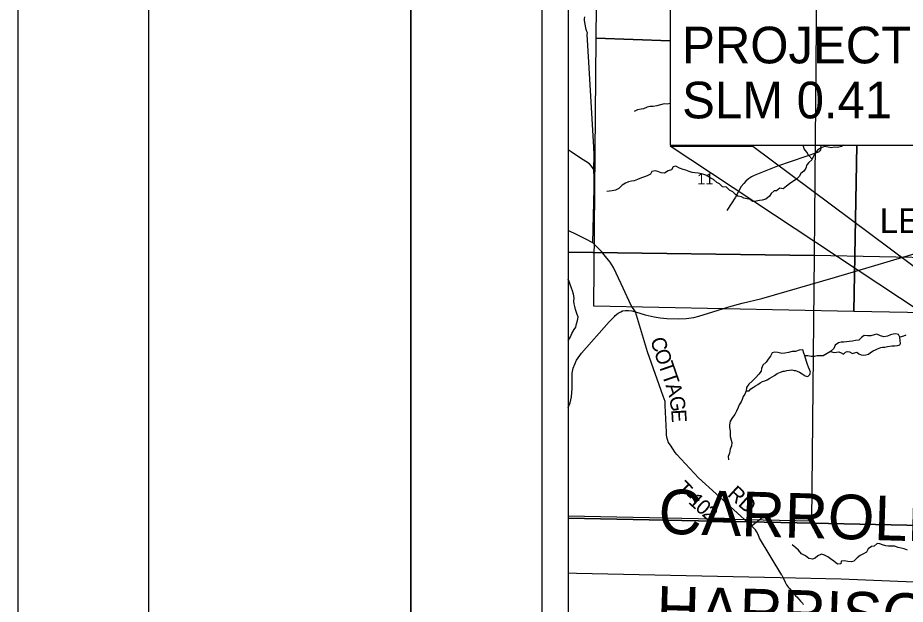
# Model space of a CAD drawing. Extents: x -19.9 to 41.9, y 0 to 32.3.
# Drawn here: x 0 to 3.386, y 17.59 to 19.829 of the extents above; entities that cross this region are included whole.
import ezdxf

# ---------------------------------------------------------------- set-up
doc = ezdxf.new("R2010")
doc.units = 0
for name, color, linetype in [('GM_X_Corporation', 7, 'Continuous'), ('GM_X_Corporation_Text', 7, 'Continuous'), ('GM_X_County', 7, 'Continuous'), ('GM_X_County_Road', 7, 'Continuous'), ('GM_X_County_Text', 7, 'Continuous'), ('GM_X_Minor_Lake', 7, 'Continuous'), ('GM_X_Minor_River', 7, 'Continuous'), ('GM_X_Section', 7, 'Continuous'), ('GM_X_Section_Text', 7, 'Continuous'), ('GM_X_Township_Road', 7, 'Continuous'), ('GM_X_Township_Road_Text', 7, 'Continuous'), ('SH_Border', 7, 'Continuous'), ('SH_Cut_Line', 7, 'Continuous'), ('SH_Data', 7, 'Continuous'), ('SH_Text', 7, 'Continuous')]:
    doc.layers.add(name, color=color, linetype=linetype)

msp = doc.modelspace()

# ---------------------------------------------------------------- linework, layer by layer
at = {"layer": 'GM_X_Corporation'}
for points in [[(8.9, 17.8974), (8.9, 20.9), (2.1, 20.9), (2.1, 17.918), (2.4715, 17.9106), (2.973, 17.9007), (3.7505, 17.884), (3.984, 17.879), (4.2613, 17.8672), (4.9169, 17.8392), (5.0192, 17.8403), (5.0257, 17.9637), (5.4954, 17.9559), (5.761, 17.9543), (5.9048, 17.9534), (6.2397, 17.9517), (6.2497, 17.9517), (6.3069, 17.9505), (6.7, 17.9422), (6.9468, 17.937), (7.3858, 17.9277), (7.5529, 17.9242), (7.9072, 17.9171)], [(2.1, 19.9743), (2.1, 18.9334), (3.0393, 18.921), (3.0491, 19.9448)], [(3.0491, 19.9448), (4.0503, 19.9079), (4.0319, 18.9009), (3.0393, 18.921)], [(2.1, 18.9334), (2.1, 17.9274), (3.0296, 17.9081), (3.0393, 18.921)], [(2.1, 17.918), (2.1, 14.1), (8.9, 14.1), (8.9, 17.8974), (7.9072, 17.9171), (7.5529, 17.9242), (7.3858, 17.9277), (6.9468, 17.937), (6.7, 17.9422), (6.3069, 17.9505), (6.2497, 17.9517), (6.2397, 17.9517), (5.9048, 17.9534), (5.761, 17.9543), (5.4954, 17.9559), (5.0257, 17.9637), (5.0192, 17.8403), (4.9169, 17.8392), (4.2613, 17.8672), (3.984, 17.879), (3.7505, 17.884), (2.973, 17.9007), (2.4715, 17.9106)]]:
    msp.add_lwpolyline(points, close=True, dxfattribs=at)
for points in [[(7.9833, 20.9), (2.1, 20.9), (2.1, 17.918), (2.4715, 17.9106), (2.973, 17.9007), (3.7505, 17.884)], [(7.9012, 17.4524), (7.9072, 17.9171), (7.5529, 17.9242), (7.3858, 17.9277), (6.9468, 17.937), (6.7, 17.9422), (6.3069, 17.9505), (6.2497, 17.9517), (6.2397, 17.9517), (5.9048, 17.9534), (5.761, 17.9543), (5.4954, 17.9559), (5.0257, 17.9637), (5.0192, 17.8403), (4.9169, 17.8392), (4.2613, 17.8672), (3.984, 17.879), (3.7505, 17.884), (2.973, 17.9007), (2.4715, 17.9106), (2.1, 17.918), (2.1, 14.1)]]:
    msp.add_lwpolyline(points, dxfattribs=at)
at = {"layer": 'GM_X_County'}
msp.add_lwpolyline([(8.9, 17.6915), (8.8006, 17.694), (8.0736, 17.7036), (7.0652, 17.7237), (6.7109, 17.7307), (6.5438, 17.7343), (6.1048, 17.7436), (5.8581, 17.7488), (5.4649, 17.757), (5.4078, 17.7582), (5.3977, 17.7582), (5.0628, 17.7599), (4.9191, 17.7608), (4.6534, 17.7624), (4.1838, 17.7703), (4.1772, 17.6468), (4.0749, 17.6457), (3.4193, 17.6737), (3.142, 17.6855), (2.9085, 17.6906), (2.1311, 17.7073), (2.1, 17.7079)], dxfattribs=at)
at = {"layer": 'GM_X_County_Road'}
for points in [[(2.1, 18.3405), (2.1004, 18.3412), (2.1075, 18.3591), (2.1126, 18.382), (2.1155, 18.4131), (2.1154, 18.4717), (2.1195, 18.4907), (2.1318, 18.5216), (2.151, 18.5483), (2.2558, 18.6682), (2.2763, 18.689), (2.2796, 18.692), (2.2903, 18.7008), (2.3008, 18.7067), (2.3077, 18.7095), (2.3181, 18.7117), (2.3301, 18.7117), (2.3424, 18.7104), (2.3563, 18.7061), (2.3934, 18.6948), (2.4282, 18.6867), (2.4512, 18.6835), (2.4757, 18.6807), (2.5215, 18.6793), (2.5505, 18.6809), (2.5799, 18.6848), (2.5985, 18.6897), (2.6523, 18.7065), (2.7127, 18.7248), (2.764, 18.7393), (2.8384, 18.7568), (3.1193, 18.8382), (3.4928, 18.9488)], [(2.9151, 17.7005), (2.9213, 17.6879), (2.9282, 17.6737), (2.9304, 17.6695), (2.9333, 17.6645), (2.9368, 17.6594), (2.9408, 17.6537), (2.9443, 17.6493), (2.9594, 17.6317), (2.9637, 17.6268), (2.9688, 17.6212), (2.9722, 17.6176), (2.9802, 17.6091), (2.9867, 17.6019), (2.9903, 17.5977), (2.9935, 17.5936), (2.9956, 17.591), (2.9973, 17.5884)]]:
    msp.add_lwpolyline(points, dxfattribs=at)
at = {"layer": 'GM_X_Minor_Lake'}
for points in [[(3.3654, 18.61), (3.3596, 18.6198), (3.3501, 18.622), (3.3399, 18.6204), (3.33, 18.6185), (3.3179, 18.6138), (3.3039, 18.6103), (3.2909, 18.6143), (3.2772, 18.6207), (3.2673, 18.6179), (3.2541, 18.6148), (3.2415, 18.615), (3.2286, 18.6157), (3.2188, 18.6084), (3.209, 18.5981), (3.1957, 18.5972), (3.1851, 18.5937), (3.1722, 18.5928), (3.162, 18.5912), (3.1513, 18.5907), (3.1418, 18.5899), (3.1316, 18.5883), (3.1188, 18.5783), (3.1128, 18.5665), (3.1011, 18.555)], [(3.1011, 18.555), (3.1148, 18.5506), (3.1232, 18.5518), (3.1319, 18.553), (3.141, 18.55), (3.1502, 18.5448), (3.1574, 18.5524), (3.1649, 18.5548), (3.1737, 18.553), (3.1844, 18.547), (3.1927, 18.5501), (3.201, 18.5521), (3.2094, 18.5464), (3.2182, 18.5423), (3.227, 18.5405), (3.2353, 18.5417), (3.2452, 18.5452), (3.2535, 18.5506), (3.2633, 18.5568), (3.2724, 18.5614), (3.2803, 18.5645), (3.2928, 18.5695), (3.2989, 18.5707), (3.3084, 18.5712), (3.3178, 18.5736), (3.3345, 18.5767), (3.3463, 18.5768), (3.3566, 18.5777), (3.3656, 18.5797), (3.3675, 18.5854), (3.3659, 18.596), (3.3654, 18.61)], [(3.0025, 18.5382), (2.9994, 18.5484), (2.9947, 18.5609), (2.9814, 18.56), (2.9667, 18.5553), (2.9545, 18.5545), (2.9409, 18.5509), (2.9265, 18.5485), (2.9151, 18.5466), (2.8999, 18.5506), (2.8881, 18.552), (2.8778, 18.5496), (2.8723, 18.5363), (2.8628, 18.5256), (2.8554, 18.5134), (2.8429, 18.503), (2.8381, 18.4893), (2.8366, 18.4794), (2.8276, 18.4683), (2.8144, 18.4546), (2.8016, 18.4419), (2.7888, 18.4297), (2.7806, 18.4167), (2.7795, 18.4049)], [(2.7795, 18.4049), (2.7898, 18.405), (2.7973, 18.4119), (2.8064, 18.4184), (2.8151, 18.4234), (2.8234, 18.4292), (2.8325, 18.4357), (2.8408, 18.4396), (2.8503, 18.4427), (2.8597, 18.447), (2.8695, 18.4535), (2.8779, 18.4578), (2.8877, 18.4636), (2.8975, 18.4705), (2.91, 18.4763), (2.9198, 18.4794), (2.9255, 18.4802), (2.9346, 18.4826), (2.9445, 18.4838), (2.9528, 18.4842), (2.962, 18.4828), (2.9677, 18.4817), (2.9738, 18.4791), (2.9822, 18.4754), (2.9932, 18.469), (3.0035, 18.4623), (3.0138, 18.4597), (3.0213, 18.4674), (3.0243, 18.4761), (3.0204, 18.4856), (3.0166, 18.4947), (3.0127, 18.5053), (3.0088, 18.5166), (3.0025, 18.5382)]]:
    msp.add_lwpolyline(points, dxfattribs=at)
at = {"layer": 'GM_X_Minor_River'}
for points in [[(2.4893, 19.502), (2.4776, 19.4995), (2.4655, 19.5001), (2.4518, 19.497), (2.4386, 19.4931), (2.4242, 19.4899), (2.4116, 19.4902), (2.4018, 19.4874), (2.3878, 19.4812), (2.3779, 19.4796), (2.3639, 19.4769), (2.3518, 19.4711)], [(3.1502, 19.3423), (3.1502, 19.3423), (3.1502, 19.3423), (3.1426, 19.3375), (3.1275, 19.3332), (3.1153, 19.3354), (3.1032, 19.3319), (3.0917, 19.3352), (3.078, 19.3374), (3.0656, 19.3323), (3.052, 19.3246), (3.0414, 19.3101), (3.0336, 19.296), (3.0299, 19.2861), (3.0182, 19.2765), (3.0099, 19.267), (3.0066, 19.2552), (2.9995, 19.2437), (2.9878, 19.2337), (2.9818, 19.2235), (2.9709, 19.2131), (2.9573, 19.2043), (2.9441, 19.1954), (2.9324, 19.1862), (2.9203, 19.1755), (2.9078, 19.1788), (2.8953, 19.1677), (2.8854, 19.1676), (2.8749, 19.158), (2.8674, 19.1481), (2.8538, 19.1366), (2.8405, 19.1319), (2.8299, 19.1307), (2.8174, 19.1291), (2.8037, 19.1278), (2.7942, 19.1346), (2.7828, 19.1382), (2.7706, 19.14), (2.7607, 19.1453), (2.7474, 19.1482), (2.7378, 19.1546), (2.7286, 19.1647), (2.716, 19.1711), (2.7034, 19.1823), (2.6893, 19.1837), (2.6778, 19.1954), (2.6671, 19.2002), (2.6545, 19.2108), (2.6412, 19.2178), (2.6285, 19.2265), (2.6179, 19.2302), (2.6084, 19.2335), (2.5962, 19.2353), (2.5833, 19.2371), (2.573, 19.2385), (2.5619, 19.2414), (2.5494, 19.2466), (2.5391, 19.2496), (2.525, 19.2544), (2.5112, 19.2626), (2.4999, 19.2603), (2.4939, 19.2484), (2.481, 19.2445), (2.467, 19.2357), (2.4541, 19.2375), (2.4419, 19.2423), (2.4312, 19.2449), (2.4195, 19.2417), (2.4135, 19.2318), (2.4014, 19.226), (2.3916, 19.2221), (2.3798, 19.2179), (2.3643, 19.2116), (2.3511, 19.2066), (2.3416, 19.2046), (2.3302, 19.2019), (2.3185, 19.1968), (2.306, 19.1895), (2.2932, 19.1769), (2.28, 19.1703), (2.2675, 19.1679), (2.258, 19.1667), (2.2477, 19.1655)], [(3.0311, 19.2894), (3.0164, 19.3046), (3.0099, 19.3159), (3.0003, 19.3291), (2.9963, 19.342), (2.9964, 19.3423)], [(2.1, 18.595), (2.1, 18.5951), (2.1082, 18.6103), (2.1141, 18.6237), (2.123, 18.6382), (2.1297, 18.6478), (2.1322, 18.6607), (2.1351, 18.6733), (2.138, 18.6854), (2.1333, 18.6998), (2.1278, 18.7145), (2.1258, 18.7267), (2.1223, 18.7365), (2.1214, 18.746), (2.1224, 18.7596), (2.1196, 18.774), (2.116, 18.7865), (2.1121, 18.7967), (2.1071, 18.8111), (2.1035, 18.8217), (2.1, 18.8311)], [(3.3885, 18.6167), (3.3787, 18.6136), (3.3654, 18.61), (3.3596, 18.6198), (3.3501, 18.622), (3.3399, 18.6204), (3.33, 18.6185), (3.3179, 18.6138), (3.3039, 18.6103), (3.2909, 18.6143), (3.2772, 18.6207), (3.2673, 18.6179), (3.2541, 18.6148), (3.2415, 18.615), (3.2286, 18.6157), (3.2188, 18.6084), (3.209, 18.5981), (3.1957, 18.5972), (3.1851, 18.5937), (3.1722, 18.5928), (3.162, 18.5912), (3.1513, 18.5907), (3.1418, 18.5899), (3.1316, 18.5883), (3.1188, 18.5783), (3.1128, 18.5665), (3.1011, 18.555), (3.0883, 18.5473), (3.0728, 18.5384), (3.0496, 18.5382), (3.0401, 18.5359), (3.0268, 18.5357), (3.0139, 18.5383), (3.0025, 18.5382), (2.9994, 18.5484), (2.9947, 18.5609), (2.9814, 18.56), (2.9667, 18.5553), (2.9545, 18.5545), (2.9409, 18.5509), (2.9265, 18.5485), (2.9151, 18.5466), (2.8999, 18.5506), (2.8881, 18.552), (2.8778, 18.5496), (2.8723, 18.5363), (2.8628, 18.5256), (2.8554, 18.5134), (2.8429, 18.503), (2.8381, 18.4893), (2.8366, 18.4794), (2.8276, 18.4683), (2.8144, 18.4546), (2.8016, 18.4419), (2.7888, 18.4297), (2.7806, 18.4167), (2.7795, 18.4049), (2.7736, 18.392), (2.768, 18.3824), (2.7635, 18.3721), (2.7594, 18.3626), (2.7526, 18.3511), (2.7486, 18.3409), (2.7415, 18.3275), (2.7351, 18.3142), (2.7268, 18.3027), (2.7178, 18.289), (2.7157, 18.2749), (2.7158, 18.265), (2.7174, 18.2521), (2.7182, 18.2411), (2.7183, 18.2301), (2.7219, 18.2168), (2.7238, 18.207), (2.7224, 18.1941), (2.718, 18.1815), (2.7151, 18.1663)], [(2.7151, 18.1663), (2.7102, 18.1533), (2.7115, 18.1412)], [(3.3943, 17.7959), (3.3817, 17.8015), (3.3703, 17.8044), (3.3589, 17.8062), (3.3451, 17.8114), (3.322, 17.8112), (3.3117, 17.8126), (3.2991, 17.8163), (3.2888, 17.8208), (3.2793, 17.8211), (3.2669, 17.8115), (3.2566, 17.8107), (3.2446, 17.8018), (3.2378, 17.7888), (3.2238, 17.7811), (3.2133, 17.7757), (3.2019, 17.7669), (3.1899, 17.7539), (3.1804, 17.7519), (3.1663, 17.7533), (3.1534, 17.7558), (3.142, 17.7546), (3.1395, 17.744), (3.1277, 17.7431), (3.1135, 17.754), (3.1002, 17.7634), (3.0902, 17.7705), (3.0784, 17.7772), (3.0662, 17.7805), (3.0522, 17.7751), (3.0417, 17.7659), (3.0318, 17.762), (3.0181, 17.7649), (3.0051, 17.7747), (2.9906, 17.7829), (2.9787, 17.7965), (2.9684, 17.8047), (2.9546, 17.8171)]]:
    msp.add_lwpolyline(points, dxfattribs=at)
at = {"layer": 'GM_X_Section'}
for points in [[(2.4893, 19.7409), (2.2072, 19.7514), (2.2165, 20.721), (3.2305, 20.7127), (3.2116, 19.8611)], [(3.2015, 19.3423), (3.19, 18.7074), (2.1973, 18.7275), (2.2072, 19.7514), (2.4893, 19.7409)], [(4.2222, 19.3423), (4.2131, 18.8031), (4.2117, 18.6878), (3.19, 18.7074), (3.2015, 19.3423)]]:
    msp.add_lwpolyline(points, dxfattribs=at)
at = {"layer": 'GM_X_Township_Road'}
msp.add_line((2.198, 19.3346), (2.1786, 19.6589), dxfattribs=at)
for points in [[(2.1786, 19.6589), (2.1722, 19.7646), (2.1731, 19.7715), (2.1711, 19.777), (2.1689, 19.7842), (2.1631, 19.8113), (2.1627, 19.8196), (2.1625, 19.825), (2.1635, 19.832)], [(2.9151, 17.7005), (2.8302, 17.8422), (2.8246, 17.8562), (2.819, 17.8675), (2.8151, 17.8738), (2.8135, 17.8756), (2.8039, 17.8843), (2.799, 17.8888), (2.5972, 18.0723), (2.5141, 18.1617), (2.5081, 18.1694), (2.4899, 18.1967), (2.4857, 18.2034), (2.4819, 18.2103), (2.4803, 18.2148), (2.478, 18.2231), (2.4755, 18.2356), (2.4745, 18.2474), (2.4701, 18.3488), (2.4699, 18.3605), (2.4695, 18.3636), (2.4623, 18.3848), (2.4026, 18.5529), (2.3563, 18.7061), (2.3407, 18.73), (2.3019, 18.8131), (2.2731, 18.8751), (2.2599, 18.8959), (2.2424, 18.9175), (2.2266, 18.9366), (2.2153, 18.9482), (2.2063, 18.9572), (2.1946, 18.9692), (2.1994, 19.1769), (2.1988, 19.2147), (2.1985, 19.2261), (2.1983, 19.2401), (2.1978, 19.2498), (2.1997, 19.3058), (2.198, 19.3346)], [(3.0615, 19.3423), (3.0615, 19.3423), (3.0615, 19.3423), (3.0629, 19.34), (3.064, 19.3369), (3.0649, 19.3332), (3.0644, 19.3292), (3.0624, 19.3244), (3.0603, 19.3208), (3.0579, 19.318), (3.0553, 19.3163), (2.8989, 19.2626), (2.8097, 19.2265), (2.7987, 19.2214), (2.7878, 19.2139), (2.7777, 19.2052), (2.7696, 19.1966), (2.7601, 19.1842), (2.7383, 19.1443), (2.7052, 19.0925)], [(2.1978, 19.2498), (2.1926, 19.257), (2.188, 19.2641), (2.1807, 19.2712), (2.1434, 19.2952), (2.1111, 19.3175), (2.1, 19.3252)], [(2.1946, 18.9692), (2.1672, 18.9832), (2.1342, 18.9996), (2.1, 19.0163)], [(2.799, 17.8888), (2.8469, 17.9262), (2.8533, 17.9299), (2.8878, 17.9436)]]:
    msp.add_lwpolyline(points, dxfattribs=at)
at = {"layer": 'SH_Border'}
for points in [[(0.5, 21.5), (1.5, 21.5), (1.5, 0.5), (0.5, 0.5)], [(1.5, 21.5), (33.5, 21.5), (33.5, 0.5), (1.5, 0.5)]]:
    msp.add_lwpolyline(points, close=True, dxfattribs=at)
at = {"layer": 'SH_Cut_Line'}
msp.add_lwpolyline([(0, 0), (34, 0), (34, 22), (0, 22)], close=True, dxfattribs=at)
at = {"layer": 'SH_Data'}
for p, q in [((2, 21), (2, 14)), ((2.1, 20.9), (2.1, 14.1))]:
    msp.add_line(p, q, dxfattribs=at)
at = {"layer": 'SH_Text'}
for points in [[(2.4893, 19.3423), (4.3977, 19.3423), (4.3977, 19.8611), (2.4893, 19.8611)], [(2.8043, 19.3392), (5.2749, 17.495), (2.4893, 19.3392)]]:
    msp.add_lwpolyline(points, close=True, dxfattribs=at)

# ---------------------------------------------------------------- texts
at = {"layer": 'GM_X_Corporation_Text'}
msp.add_text('LEESVILLE', height=0.0947, rotation=0, dxfattribs=at).set_placement((3.2887, 19.0067))
at = {"layer": 'GM_X_County_Text'}
for s, p in [('CARROLL COUNTY', (2.4429, 17.8593)), ('HARRISON COUNTY', (2.4348, 17.4893))]:
    msp.add_text(s, height=0.170455, rotation=358.3166, dxfattribs=at).set_placement(p)
at = {"layer": 'GM_X_Section_Text'}
msp.add_text('11', height=0.04186, rotation=0, dxfattribs=at).set_placement((2.592, 19.1925))
at = {"layer": 'GM_X_Township_Road_Text'}
for s, height, rotation, p in [('C', 0.0568, 286.7735, (2.4127, 18.6001)), ('O', 0.0568, 288.7053, (2.4268, 18.5534)), ('T', 0.0568, 289.102, (2.443, 18.5056)), ('T', 0.0568, 289.1011, (2.4569, 18.4655)), ('A', 0.0568, 287.4097, (2.4707, 18.4257)), ('G', 0.0568, 279.2159, (2.4851, 18.3801)), ('E', 0.0568, 273.3511, (2.493, 18.3323)), ('T', 0.0568, 314.0469, (2.5058, 18.027)), ('RD', 0.05682, 317.7918, (2.7045, 18.0057)), ('-', 0.0568, 317.0684, (2.5377, 17.9941)), ('1', 0.0568, 317.6344, (2.5552, 17.9778)), ('0', 0.0568, 317.9517, (2.5813, 17.954)), ('2', 0.0568, 318.0315, (2.6074, 17.9305))]:
    msp.add_text(s, height=height, rotation=rotation, dxfattribs=at).set_placement(p)
at = {"layer": 'SH_Text'}
for s, p in [('PROJECT LOCATION', (2.5347, 19.6548)), ('SLM 0.41', (2.5347, 19.4448))]:
    msp.add_text(s, height=0.14, dxfattribs=at).set_placement(p)

doc.saveas('drawing.dxf')
